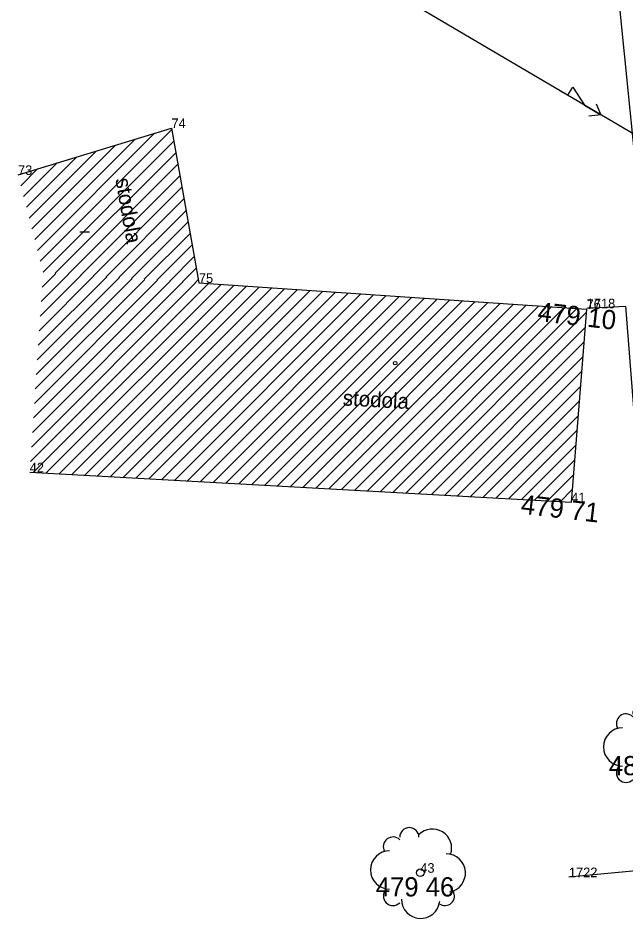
# Model space of a CAD drawing. Extents: x -559180 to -551373, y -1076947 to -1072071.
# Drawn here: x -553581.61 to -553549.91, y -1076065.15 to -1076018.21 of the extents above; entities that cross this region are included whole.
import ezdxf

# ---------------------------------------------------------------- set-up
doc = ezdxf.new("R2010")
doc.units = 0
for name, color, linetype in [('12_PLOTY', 7, 'Continuous'), ('14_BUDOVY', 7, 'Continuous'), ('17_KOMUNIKACE', 7, 'Continuous'), ('1_VODA_ZN', 7, 'Continuous'), ('20_EL_ZN', 7, 'Continuous'), ('32', 7, 'Continuous'), ('34_ZELEN', 7, 'Continuous'), ('3_BODY', 7, 'Continuous'), ('47_ZN_STAV_OBJ$', 7, 'Continuous'), ('52_POPIS_UCELOVY', 7, 'Continuous'), ('6_VYSKY', 7, 'Continuous'), ('NNnadzemní', 7, 'Continuous')]:
    doc.layers.add(name, color=color, linetype=linetype)

# ---------------------------------------------------------------- blocks, each defined once
blk = doc.blocks.new('POINT_DISPLAY')
blk.add_line((0, 0), (0, 0))
blk = doc.blocks.new('STLS')
at = {"layer": '34_ZELEN'}
blk.add_circle((0, 0), 0.2, dxfattribs=at)
for centre, radius, start, end in [((-0.571, 1.853), 0.5, 0, 180), ((0.636, 1.281), 1, 341.2293, 135), ((-1.425, 1.366), 0.5, 45, 210.4326), ((-1.599, 0.146), 1, 90, 270), ((1.356, -0.015), 1, 279.53, 90), ((-1.424, -1.207), 0.5, 135, 315), ((0.019, -1.381), 1, 180, 353.8403), ((1.283, -1.208), 0.5, 234.3777, 31.0479)]:
    blk.add_arc(centre, radius, start, end, dxfattribs=at)
blk = doc.blocks.new('BZ')
at = {"layer": '47_ZN_STAV_OBJ$'}
blk.add_circle((0, 0), 0.0875, dxfattribs=at)
blk = doc.blocks.new('BD')
at = {"layer": '47_ZN_STAV_OBJ$'}
blk.add_line((-0.25, 0), (0.25, 0), dxfattribs=at)
blk = doc.blocks.new('ELNN')
at = {"layer": '20_EL_ZN'}
for p, q in [((0.5, 0), (0.5, 0.5)), ((0.5, 0.5), (1.5, 0)), ((0, 0), (0.5, 0)), ((1.5, 0), (2.5, 0))]:
    blk.add_line(p, q, dxfattribs=at)
blk.add_lwpolyline([(2, 0.375), (2.5, 0), (2, -0.375)], dxfattribs=at)

msp = doc.modelspace()

# ---------------------------------------------------------------- linework, layer by layer
at = {"layer": '12_PLOTY'}
for p, q in [((-553551.96, -1076033.33), (-553549.94, -1076033.22)), ((-553549.94, -1076033.22), (-553548.74, -1076048.64)), ((-553547.6, -1076062.46), (-553552.89, -1076062.97))]:
    msp.add_line(p, q, dxfattribs=at)
at = {"layer": '14_BUDOVY'}
for p, q in [((-553581.61, -1076026.38), (-553573.61, -1076023.94)), ((-553573.61, -1076023.94), (-553572.18, -1076032.01)), ((-553572.18, -1076032.01), (-553551.97, -1076033.37)), ((-553551.97, -1076033.37), (-553552.77, -1076043.44)), ((-553552.77, -1076043.44), (-553581, -1076041.88))]:
    msp.add_line(p, q, dxfattribs=at)
at = {"layer": '17_KOMUNIKACE'}
msp.add_line((-553550.6, -1076014.27), (-553547.29, -1076047.21), dxfattribs=at)
at = {"layer": '32'}
for p, q in [((-553580.45, -1076030.877), (-553573.595, -1076024.022)), ((-553580.74, -1076029.753), (-553575.505, -1076024.518)), ((-553580.595, -1076030.315), (-553574.488, -1076024.208)), ((-553580.885, -1076029.191), (-553576.523, -1076024.828)), ((-553580.305, -1076031.439), (-553573.489, -1076024.623)), ((-553581.175, -1076028.066), (-553578.558, -1076025.449)), ((-553581.03, -1076028.629), (-553577.54, -1076025.139)), ((-553579.666, -1076031.507), (-553573.383, -1076025.224)), ((-553581.32, -1076027.504), (-553579.575, -1076025.759)), ((-553579.003, -1076031.551), (-553573.276, -1076025.824)), ((-553581.465, -1076026.942), (-553580.593, -1076026.07)), ((-553578.34, -1076031.596), (-553573.17, -1076026.425)), ((-553577.678, -1076031.64), (-553573.063, -1076027.026)), ((-553577.015, -1076031.685), (-553572.957, -1076027.626)), ((-553576.353, -1076031.729), (-553572.85, -1076028.227)), ((-553575.69, -1076031.774), (-553572.744, -1076028.828)), ((-553575.028, -1076031.818), (-553572.637, -1076029.428)), ((-553574.365, -1076031.863), (-553572.531, -1076030.029)), ((-553573.703, -1076031.908), (-553572.425, -1076030.63)), ((-553580.401, -1076032.98), (-553578.974, -1076031.553)), ((-553580.35, -1076032.222), (-553579.636, -1076031.509)), ((-553573.04, -1076031.952), (-553572.318, -1076031.23)), ((-553580.962, -1076041.32), (-553571.686, -1076032.043)), ((-553580.911, -1076040.562), (-553572.349, -1076031.999)), ((-553580.86, -1076039.803), (-553573.011, -1076031.954)), ((-553580.809, -1076039.045), (-553573.674, -1076031.91)), ((-553580.758, -1076038.287), (-553574.336, -1076031.865)), ((-553580.707, -1076037.529), (-553574.999, -1076031.821)), ((-553580.656, -1076036.771), (-553575.661, -1076031.776)), ((-553580.605, -1076036.013), (-553576.324, -1076031.731)), ((-553580.554, -1076035.255), (-553576.986, -1076031.687)), ((-553580.503, -1076034.497), (-553577.649, -1076031.642)), ((-553580.452, -1076033.738), (-553578.311, -1076031.598)), ((-553572.377, -1076031.997), (-553572.212, -1076031.831)), ((-553580.825, -1076041.89), (-553571.024, -1076032.088)), ((-553580.155, -1076041.927), (-553570.361, -1076032.133)), ((-553579.485, -1076041.964), (-553569.699, -1076032.177)), ((-553578.815, -1076042.001), (-553569.036, -1076032.222)), ((-553578.145, -1076042.038), (-553568.373, -1076032.266)), ((-553577.475, -1076042.075), (-553567.711, -1076032.311)), ((-553576.805, -1076042.112), (-553567.048, -1076032.356)), ((-553576.135, -1076042.149), (-553566.386, -1076032.4)), ((-553575.465, -1076042.186), (-553565.723, -1076032.445)), ((-553574.794, -1076042.223), (-553565.061, -1076032.489)), ((-553574.124, -1076042.26), (-553564.398, -1076032.534)), ((-553573.454, -1076042.297), (-553563.736, -1076032.578)), ((-553572.784, -1076042.334), (-553563.073, -1076032.623)), ((-553572.114, -1076042.371), (-553562.411, -1076032.668)), ((-553571.444, -1076042.408), (-553561.748, -1076032.712)), ((-553570.774, -1076042.445), (-553561.086, -1076032.757)), ((-553570.104, -1076042.482), (-553560.423, -1076032.801)), ((-553569.434, -1076042.519), (-553559.761, -1076032.846)), ((-553568.764, -1076042.556), (-553559.098, -1076032.89)), ((-553568.094, -1076042.593), (-553558.435, -1076032.935)), ((-553567.424, -1076042.63), (-553557.773, -1076032.98)), ((-553566.754, -1076042.667), (-553557.11, -1076033.024)), ((-553566.083, -1076042.704), (-553556.448, -1076033.069)), ((-553565.413, -1076042.741), (-553555.785, -1076033.113)), ((-553564.743, -1076042.778), (-553555.123, -1076033.158)), ((-553564.073, -1076042.815), (-553554.46, -1076033.202)), ((-553563.403, -1076042.852), (-553553.798, -1076033.247)), ((-553562.733, -1076042.889), (-553553.135, -1076033.292)), ((-553562.063, -1076042.926), (-553552.473, -1076033.336)), ((-553561.393, -1076042.963), (-553551.985, -1076033.555)), ((-553560.723, -1076043.001), (-553552.046, -1076034.323)), ((-553560.053, -1076043.038), (-553552.107, -1076035.092)), ((-553559.383, -1076043.075), (-553552.168, -1076035.86)), ((-553558.713, -1076043.112), (-553552.229, -1076036.628)), ((-553558.043, -1076043.149), (-553552.29, -1076037.396)), ((-553557.372, -1076043.186), (-553552.351, -1076038.164)), ((-553556.702, -1076043.223), (-553552.412, -1076038.932)), ((-553556.032, -1076043.26), (-553552.473, -1076039.7)), ((-553555.362, -1076043.297), (-553552.534, -1076040.468)), ((-553554.692, -1076043.334), (-553552.595, -1076041.237)), ((-553554.022, -1076043.371), (-553552.656, -1076042.005)), ((-553553.352, -1076043.408), (-553552.717, -1076042.773))]:
    msp.add_line(p, q, dxfattribs=at)
at = {"layer": 'NNnadzemní'}
msp.add_line((-553543.04, -1076028.06), (-553572.09, -1076010.97), dxfattribs=at)

# ---------------------------------------------------------------- block references
at = {"layer": '1_VODA_ZN'}
for p in [(-553573.61, -1076023.94), (-553581.61, -1076026.38), (-553572.18, -1076032.01), (-553551.97, -1076033.37), (-553551.96, -1076033.33), (-553549.94, -1076033.22), (-553581, -1076041.88), (-553552.77, -1076043.44), (-553560.64, -1076062.74), (-553552.89, -1076062.97)]:
    msp.add_blockref('POINT_DISPLAY', p, dxfattribs=at)
at = {"layer": '20_EL_ZN', "xscale": 1.00000127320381, "yscale": 1.0000012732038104, "rotation": -30.468115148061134}
msp.add_blockref('ELNN', (-553553.377, -1076021.979), dxfattribs=at)
at = {"layer": '32'}
for p in [(-553581.61, -1076026.38), (-553580.299, -1076031.464)]:
    msp.add_blockref('POINT_DISPLAY', p, dxfattribs=at)
at = {"layer": '34_ZELEN'}
for p in [(-553548.49, -1076056.33), (-553560.64, -1076062.74)]:
    msp.add_blockref('STLS', p, dxfattribs=at)
at = {"layer": '47_ZN_STAV_OBJ$'}
for name, p in [('BD', (-553578.132, -1076029.337)), ('BZ', (-553561.948, -1076036.189))]:
    msp.add_blockref(name, p, dxfattribs=at)

# ---------------------------------------------------------------- texts
at = {"layer": '3_BODY'}
for s, p in [('74', (-553573.61, -1076023.94)), ('73', (-553581.61, -1076026.38)), ('75', (-553572.18, -1076032.01)), ('76', (-553551.97, -1076033.37)), ('1718', (-553551.96, -1076033.33)), ('42', (-553581, -1076041.88)), ('41', (-553552.77, -1076043.44)), ('43', (-553560.64, -1076062.74)), ('1722', (-553552.89, -1076062.97))]:
    msp.add_text(s, height=0.5, dxfattribs=at).set_placement(p)
at = {"layer": '52_POPIS_UCELOVY'}
for rotation, p in [(280.0485, (-553576.539, -1076026.604)), (356.837, (-553564.694, -1076038.389))]:
    msp.add_text('stodola', height=0.8, rotation=rotation, dxfattribs=at).set_placement(p)
at = {"layer": '6_VYSKY'}
for s, rotation, p in [('479 10', 353.427, (-553554.555, -1076033.988)), ('479 71', 353.3278, (-553555.431, -1076044.021))]:
    msp.add_text(s, height=1, rotation=rotation, dxfattribs=at).set_placement(p)
for s, p in [('481 17', (-553550.807, -1076057.658)), ('479 46', (-553562.958, -1076063.974))]:
    msp.add_text(s, height=1, dxfattribs=at).set_placement(p)

doc.saveas('drawing.dxf')
